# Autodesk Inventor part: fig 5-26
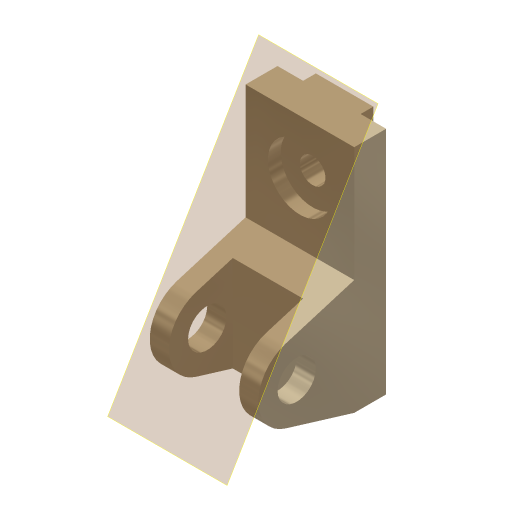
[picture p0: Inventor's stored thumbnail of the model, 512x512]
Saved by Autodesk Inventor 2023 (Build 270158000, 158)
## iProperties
Created: 2001-11
Part Number: fig 5-26
Document SubType Name: Modeling
Designer: Renu Muthoo
Density: 1 g/cm^3
Material: Generic
Appearance: Metal-Titanium (Polished)
Control State: 0
Master: False
Checked Out: False
Shininess: 65.0
Angle Display Precision: 2
Document Length Units: 11269
Document Angle Units: 11279
Document Time Units: 11290
Document Mass Units: 11283
Document Length Units Precision: 3
Document Angle Units Precision: 2
Compacted: False
Density: 0.0
Volumn: 0.0
Area: 0.0
PropertySet Name: Model Information
Author: Renu Muthoo
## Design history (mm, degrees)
node "Sketch1"
sketch "Sketch2"
  geometry: L1 (33.257, 104.664)-(33.257, -75.336); L2 (33.257, -75.336)-(8.257, -75.336); L3 (8.257, -75.336)-(-45.451, -59.045); L4 (-45.451, -1.628)-(8.257, 14.664); L5 (8.257, 14.664)-(8.257, 104.664); L6 (8.257, 104.664)-(33.257, 104.664); C1 r 15 at (-36.743, -30.336); A1 r 30 centre (-36.743, -30.336) between (-45.451, -1.628) and (-45.451, -59.045)
  constraints: 12 end point, 2 centre point, 2 equal length, 2 parallel, 2 point on circle, 2 tangent, 1 coincident, 1 perpendicular, 1 vertical
  dimensions: "d0" = 180 distance of L1.start L1.end; "d1" = 30 radius of A1; "d2" = 25 distance of L5.end L1.start; "d3" = 45 distance from line of L2 A1.centre; "d4" = 70 distance from line of L1 A1.centre; "d5" = 30 diameter of C1
extrude "Extrusion1" new body sketch "Sketch2" distance "d6" = 85; taper "d7" = 0 deg
workplane "Work Plane1"
sketch "Sketch3"
  geometry: L1 (15, 62.364)-(70, 62.364); L2 (70, 62.364)-(70, -52.386); L3 (70, -52.386)-(15, -52.386); L4 (15, -52.386)-(15, 62.364); L5 (0, -45)-(0, -28.708) reference
  constraints: 8 end point, 2 parallel, 1 horizontal, 1 perpendicular
  dimensions: "d8" = 55 distance of L1.start L1.end; "d9" = 15 distance between parallel lines of L5 L4
extrude "Extrusion2" cut sketch "Sketch3" distance "d10" = 50; taper "d11" = 0 deg
sketch "Sketch4"
  geometry: L1 (0, 25)-(85, 25) reference; L2 (0, 0)-(0, 25) reference; L3 (20, 25)-(65, 25); L4 (65, 25)-(65, 35); L5 (65, 35)-(20, 35); L6 (20, 35)-(20, 25)
  constraints: 8 end point, 2 parallel, 1 horizontal, 1 perpendicular, 1 point on line
  dimensions: "d12" = 45 distance of L4.end L5.end; "d13" = 10 distance of L3.end L4.end; "d14" = 20 distance between parallel lines of L2 L6
extrude "Extrusion3" join sketch "Sketch4" stored distance "d15" = 50; taper "d16" = 0 deg
sketch "Sketch5"
  geometry: L1 (85, 0)-(85, 90) reference; L2 (0, 90)-(85, 90) reference; 1 further point
  dimensions: "d17" = 42 distance from line of L2 point (42.5, 48); "d18" = 42.5 distance from line of L1 point (42.5, 48)
hole "Hole1" sketch "Sketch5" at (42.5, 48) diameter "d19" = 20; stored, may be unused: countersink angle "d23" = 82 deg, drill point angle "d25" = 118 deg; dims "d20" = 6, "d21" = 50, "d22" = 10, "d24" = 8
workplane "Work Plane12"
body "Solid1"
